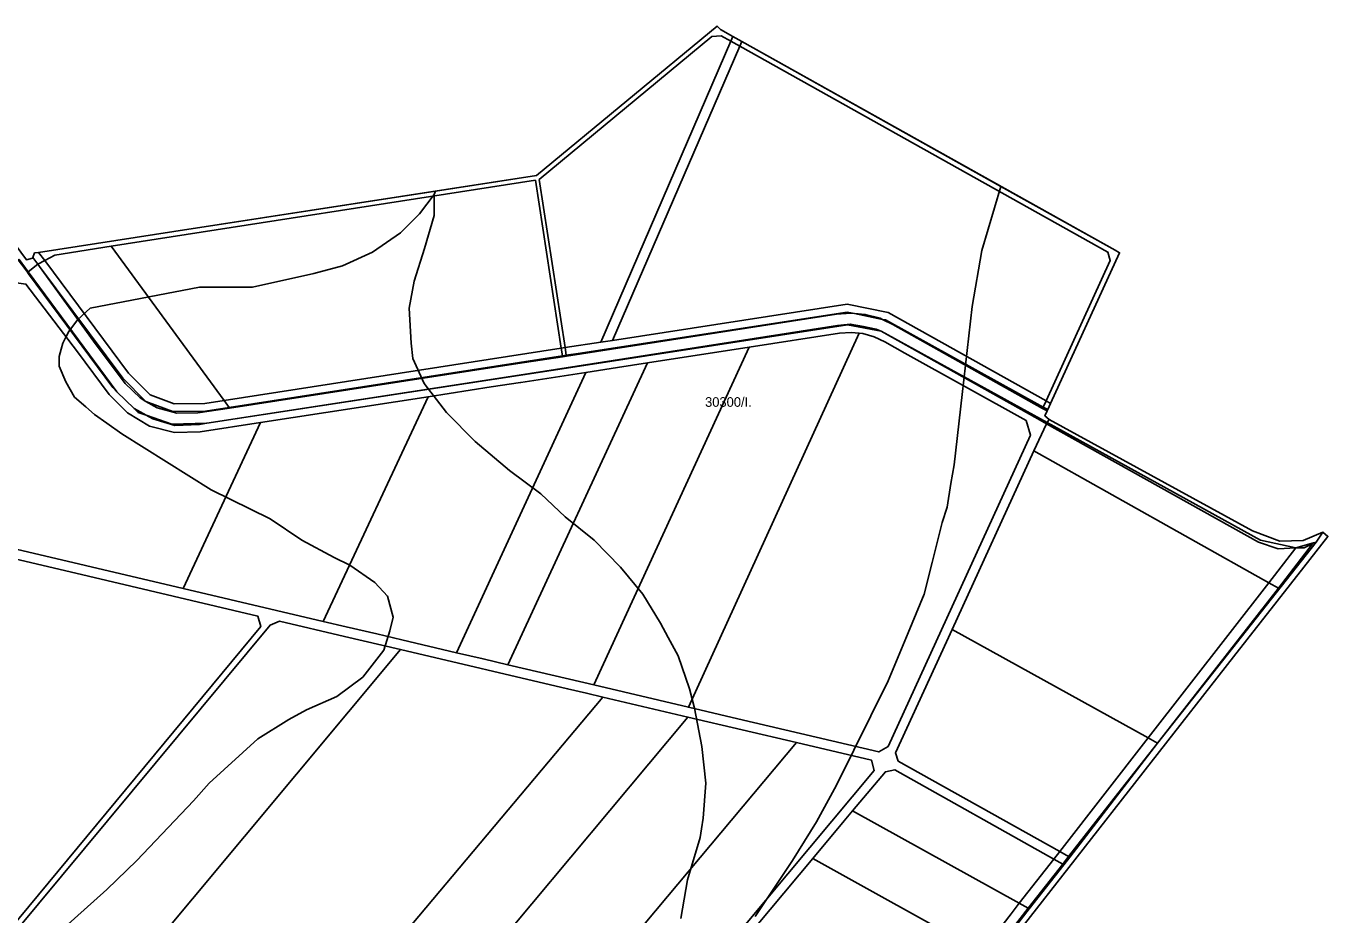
# Model space of a CAD drawing. Extents: x -541351 to -537540, y -1162694 to -1159725.
# Drawn here: x -538214 to -537540, y -1160910 to -1160450 of the extents above; entities that cross this region are included whole.
import ezdxf

# ---------------------------------------------------------------- set-up
doc = ezdxf.new("R2010")
doc.units = 0
for name, color, linetype in [('95560013', 7, 'Continuous'), ('95630013', 7, 'Continuous'), ('95640013', 7, 'Continuous'), ('95660013', 7, 'Continuous')]:
    doc.layers.add(name, color=color, linetype=linetype)

msp = doc.modelspace()

# ---------------------------------------------------------------- linework, layer by layer
at = {"layer": '95560013'}
for points in [[(-537854.65, -1160451.57), (-537848.19, -1160455.22), (-537849.25, -1160457.68), (-537854.31, -1160454.85), (-537859.18, -1160455.32), (-537948.53, -1160529.38), (-537935.11, -1160616.38), (-537937.08, -1160616.69), (-537950.51, -1160529.69), (-538170.18, -1160563.9), (-538199.28, -1160568.43), (-538204.55, -1160571.24), (-538207.69, -1160567.02), (-538137.75, -1160556.21), (-537949.87, -1160527.25), (-537856.38, -1160449.82)], [(-537854.31, -1160454.85), (-537849.25, -1160457.68), (-537916.68, -1160613.54), (-537935.11, -1160616.38), (-537948.53, -1160529.38), (-537859.18, -1160455.32)], [(-537652.84, -1160571.2), (-537686.06, -1160643.92), (-537767.82, -1160598.23), (-537789.01, -1160593.87), (-537910.61, -1160612.61), (-537844.69, -1160460.23), (-537654.02, -1160566.9)], [(-537648.03, -1160567.22), (-537683.74, -1160645.22), (-537686.06, -1160643.92), (-537652.84, -1160571.2), (-537654.02, -1160566.9), (-537844.69, -1160460.23), (-537843.64, -1160457.79), (-537650.31, -1160565.94)], [(-538111.7, -1160643.7), (-538170.18, -1160563.9), (-537950.51, -1160529.69), (-537937.08, -1160616.69)], [(-538204.55, -1160571.24), (-538199.28, -1160568.43), (-538170.18, -1160563.9), (-538111.7, -1160643.7), (-538121.61, -1160645.23), (-538137.51, -1160645.41), (-538149.93, -1160640.74), (-538161.11, -1160629.63)], [(-538150.21, -1160657.12), (-538137.31, -1160660.37), (-538124.12, -1160660), (-538092.74, -1160655.16), (-538132.87, -1160741.07), (-538332.3, -1160694.19), (-538330, -1160691.49), (-538326.82, -1160690.99), (-538270.16, -1160628.95), (-538250.29, -1160611.47), (-538227.76, -1160588.54), (-538220.32, -1160582.71), (-538214.26, -1160583.47), (-538187.49, -1160618.51), (-538171.08, -1160640.58), (-538161.72, -1160650.17)], [(-537787, -1160608.49), (-537782.88, -1160608.89), (-537871.24, -1160802.58), (-537920.22, -1160791.07), (-537839.88, -1160616.13), (-537793.09, -1160608.9)], [(-537685.53, -1160655.19), (-537682.14, -1160657.06), (-537575.01, -1160716.01), (-537556.76, -1160720.12), (-537565.98, -1160720.56), (-537576.03, -1160717.03), (-537685.89, -1160655.77), (-537690.34, -1160653.28), (-537771.5, -1160607.84)], [(-537767.83, -1160822.91), (-537772.69, -1160825.75), (-537845.69, -1160808.59), (-537871.24, -1160802.58), (-537782.88, -1160608.89), (-537781.03, -1160609.08), (-537775.16, -1160610.75), (-537769.61, -1160613.4), (-537759.18, -1160619.21), (-537696.41, -1160654.15), (-537694.22, -1160661.78)], [(-537964.76, -1160780.6), (-537892.46, -1160624.24), (-537839.88, -1160616.13), (-537920.22, -1160791.07), (-537932.87, -1160788.09)], [(-537892.46, -1160624.24), (-537964.76, -1160780.6), (-537977.6, -1160777.58), (-537991.33, -1160774.35), (-537924.33, -1160629.16), (-537908.06, -1160626.65)], [(-537958.23, -1160634.39), (-537957.98, -1160634.36), (-537924.33, -1160629.16), (-537991.33, -1160774.35), (-538019.61, -1160767.7), (-538032.56, -1160764.66), (-538048.38, -1160760.94), (-538060.4, -1160758.11), (-538006.06, -1160641.78), (-537973.3, -1160636.72)], [(-538060.4, -1160758.11), (-538132.87, -1160741.07), (-538092.74, -1160655.16), (-538006.06, -1160641.78)], [(-538138.75, -1160656.03), (-538120.6, -1160655.48), (-538124.4, -1160656.1), (-538137.11, -1160656.74), (-538148.62, -1160653.29), (-538151.96, -1160651.42)], [(-537570.77, -1160738.12), (-537692.33, -1160669.82), (-537685.89, -1160655.77), (-537576.03, -1160717.03), (-537565.98, -1160720.56), (-537556.76, -1160720.12)], [(-537734.71, -1160762.32), (-537692.33, -1160669.82), (-537570.77, -1160738.12), (-537633.29, -1160818.47)], [(-538252.72, -1160949.62), (-538431.35, -1160907.37), (-538420.84, -1160890.16), (-538402.43, -1160854.81), (-538370.7, -1160795.06), (-538364.45, -1160778.07), (-538353.36, -1160743.92), (-538341.15, -1160706.33), (-538338.41, -1160697.91), (-538194.31, -1160731.78), (-538094.21, -1160755.38), (-538092.7, -1160760.72), (-538248.03, -1160948.16)], [(-538087.82, -1160760.1), (-538082.9, -1160758.05), (-538049.38, -1160765.95), (-538020.28, -1160772.77), (-538181.83, -1160966.29), (-538235.36, -1160953.73), (-538241.69, -1160952.23), (-538243.57, -1160947.44)], [(-537762.62, -1160830.46), (-537764.01, -1160826.27), (-537734.71, -1160762.32), (-537633.29, -1160818.47), (-537679.04, -1160877.27)], [(-538181.83, -1160966.29), (-538020.28, -1160772.77), (-537933.84, -1160793.03), (-537923.96, -1160795.35), (-537915.59, -1160797.32), (-538077.91, -1160990.66), (-538085.86, -1160988.79)], [(-538045.37, -1160998.29), (-538077.91, -1160990.66), (-537915.59, -1160797.32), (-537871.51, -1160807.67), (-537952.32, -1160904.42), (-538033.13, -1161001.17)], [(-538033.13, -1161001.17), (-537952.32, -1160904.42), (-537871.51, -1160807.67), (-537815.26, -1160820.89), (-537977.34, -1161014.29)], [(-537815.26, -1160820.89), (-537776.51, -1160829.99), (-537775.04, -1160835.28), (-537853.06, -1160928.71), (-537931.08, -1161022.13), (-537935.72, -1161024.07), (-537977.34, -1161014.29)], [(-537764.46, -1160835.08), (-537682.11, -1160881.21), (-537699.93, -1160904.11), (-537786.25, -1160856.27), (-537769.22, -1160835.97)], [(-537806.91, -1160880.9), (-537790.61, -1160861.47), (-537786.25, -1160856.27), (-537699.93, -1160904.11), (-537704.14, -1160909.52), (-537719.59, -1160929.38)], [(-537806.91, -1160880.9), (-537719.59, -1160929.38), (-537754.86, -1160974.71), (-537843.94, -1160925.28)]]:
    msp.add_lwpolyline(points, close=True, dxfattribs=at)
for points in [[(-538214.91, -1160575.46), (-538213.5, -1160577.37), (-538212.88, -1160578.2), (-538169.34, -1160637.06), (-538167.16, -1160639.19), (-538158.3, -1160647.86), (-538156.16, -1160649.95), (-538151.96, -1160651.42), (-538148.62, -1160653.29), (-538137.11, -1160656.74), (-538124.4, -1160656.1), (-538120.6, -1160655.48), (-537927.57, -1160626.04), (-537788.88, -1160604.48), (-537771.5, -1160607.84), (-537690.34, -1160653.28), (-537685.89, -1160655.77), (-537692.33, -1160669.82), (-537734.71, -1160762.32), (-537764.01, -1160826.27), (-537762.62, -1160830.46), (-537679.04, -1160877.27), (-537682.11, -1160881.21), (-537764.46, -1160835.08), (-537769.22, -1160835.97), (-537786.25, -1160856.27), (-537790.61, -1160861.47), (-537806.91, -1160880.9), (-537843.94, -1160925.28)], [(-538332.3, -1160694.19), (-538132.87, -1160741.07), (-538060.4, -1160758.11), (-538048.38, -1160760.94), (-538032.56, -1160764.66), (-538019.61, -1160767.7), (-537991.33, -1160774.35), (-537977.6, -1160777.58), (-537964.76, -1160780.6), (-537932.87, -1160788.09), (-537920.22, -1160791.07), (-537871.24, -1160802.58), (-537845.69, -1160808.59), (-537772.69, -1160825.75), (-537767.83, -1160822.91), (-537694.22, -1160661.78), (-537696.41, -1160654.15), (-537759.18, -1160619.21), (-537769.61, -1160613.4), (-537775.16, -1160610.75), (-537781.03, -1160609.08), (-537782.88, -1160608.89), (-537787, -1160608.49), (-537793.09, -1160608.9), (-537839.88, -1160616.13), (-537892.46, -1160624.24), (-537908.06, -1160626.65), (-537924.33, -1160629.16), (-537957.98, -1160634.36), (-537958.23, -1160634.39), (-537973.3, -1160636.72), (-538006.06, -1160641.78), (-538092.74, -1160655.16), (-538124.12, -1160660), (-538137.31, -1160660.37), (-538150.21, -1160657.12), (-538161.72, -1160650.17), (-538171.08, -1160640.58), (-538187.49, -1160618.51), (-538214.26, -1160583.47)], [(-538248.03, -1160948.16), (-538092.7, -1160760.72), (-538094.21, -1160755.38), (-538194.31, -1160731.78), (-538338.41, -1160697.91)], [(-537853.06, -1160928.71), (-537775.04, -1160835.28), (-537776.51, -1160829.99), (-537815.26, -1160820.89), (-537871.51, -1160807.67), (-537915.59, -1160797.32), (-537923.96, -1160795.35), (-537933.84, -1160793.03), (-538020.28, -1160772.77), (-538049.38, -1160765.95), (-538082.9, -1160758.05), (-538087.82, -1160760.1), (-538243.57, -1160947.44)]]:
    msp.add_lwpolyline(points, dxfattribs=at)
at = {"layer": '95630013'}
msp.add_lwpolyline([(-538279, -1160482.96), (-538213.92, -1160570.92), (-538210.85, -1160570.08), (-538210.69, -1160569.68), (-538208.11, -1160573.15), (-538213.09, -1160577.05), (-538217.81, -1160570.66)], dxfattribs=at)
for points in [[(-538214.91, -1160575.46), (-538218.22, -1160570.98), (-538217.81, -1160570.66), (-538213.09, -1160577.05), (-538213.5, -1160577.37)], [(-537936.41, -1160621.05), (-537934.43, -1160620.74), (-537794.55, -1160599), (-537787.2, -1160598.56), (-537785.28, -1160598.72), (-537770.7, -1160601.72), (-537765.49, -1160604.46), (-537687.87, -1160647.87), (-537685.51, -1160649.08), (-537686.66, -1160651.61), (-537684.47, -1160653.51), (-537685.53, -1160655.19), (-537771.5, -1160607.84), (-537774.09, -1160606.83), (-537780.62, -1160605.35), (-537787.44, -1160604.21), (-537794.13, -1160604.91), (-537958.92, -1160630.57), (-538120.6, -1160655.48), (-538138.75, -1160656.03), (-538151.96, -1160651.42), (-538158.3, -1160647.86), (-538167.16, -1160639.19), (-538213.09, -1160577.05), (-538208.11, -1160573.15), (-538207.25, -1160574.31), (-538179.34, -1160612.95), (-538162.82, -1160634.9), (-538155.15, -1160642.4), (-538152.14, -1160644.18), (-538146.38, -1160647.61), (-538136.17, -1160650.23), (-538125.28, -1160650.17), (-538108.81, -1160647.63), (-537959.53, -1160624.65)], [(-538164.14, -1160632.26), (-538152.14, -1160644.18), (-538155.15, -1160642.4), (-538162.82, -1160634.9), (-538179.34, -1160612.95), (-538207.25, -1160574.31)], [(-538169.34, -1160637.06), (-538212.88, -1160578.2), (-538213.5, -1160577.37), (-538213.09, -1160577.05), (-538167.16, -1160639.19)], [(-537785.28, -1160598.72), (-537787.2, -1160598.56), (-537794.55, -1160599), (-537934.43, -1160620.74), (-537934.5, -1160620.33), (-537928.39, -1160619.39), (-537789.11, -1160597.93)], [(-537687.87, -1160647.87), (-537765.49, -1160604.46), (-537770.7, -1160601.72), (-537769.21, -1160602.03), (-537687.55, -1160647.19)], [(-537788.88, -1160604.48), (-537927.57, -1160626.04), (-538120.6, -1160655.48), (-537958.92, -1160630.57), (-537794.13, -1160604.91), (-537787.44, -1160604.21), (-537780.62, -1160605.35), (-537774.09, -1160606.83), (-537771.5, -1160607.84)], [(-537936.47, -1160620.64), (-537936.41, -1160621.05), (-537959.53, -1160624.65), (-538108.81, -1160647.63), (-538109.03, -1160647.34)], [(-537934.5, -1160620.33), (-537934.43, -1160620.74), (-537936.41, -1160621.05), (-537936.47, -1160620.64)], [(-538158.3, -1160647.86), (-538151.96, -1160651.42), (-538156.16, -1160649.95)], [(-538136.17, -1160650.23), (-538146.38, -1160647.61), (-538152.14, -1160644.18), (-538138.21, -1160649.42), (-538121.28, -1160649.23), (-538109.03, -1160647.34), (-538108.81, -1160647.63), (-538125.28, -1160650.17)], [(-537685.51, -1160649.08), (-537687.87, -1160647.87), (-537687.55, -1160647.19), (-537685.23, -1160648.47)], [(-537684.47, -1160653.51), (-537579.13, -1160711.27), (-537565.07, -1160716.59), (-537552.97, -1160716.32), (-537542.86, -1160712.01), (-537546.25, -1160717.06), (-537547.58, -1160717.45), (-537556.76, -1160720.12), (-537575.01, -1160716.01), (-537682.14, -1160657.06), (-537685.53, -1160655.19)], [(-537552.67, -1160730.05), (-537589.07, -1160776.48), (-537674.22, -1160885.61), (-537766.11, -1161003.04), (-537768.34, -1161000.98), (-537767.32, -1160999.7), (-537749.91, -1160977.46), (-537714.27, -1160932.34), (-537698.94, -1160912.41), (-537694.76, -1160906.98), (-537676.89, -1160884.14), (-537673.82, -1160880.18), (-537628.36, -1160821.2), (-537546.25, -1160717.06), (-537542.86, -1160712.01), (-537540.13, -1160714.12)], [(-537673.82, -1160880.18), (-537674.39, -1160879.87), (-537648.96, -1160847.33), (-537628.36, -1160821.2)], [(-537676.89, -1160884.14), (-537694.76, -1160906.98), (-537695.33, -1160906.66), (-537677.47, -1160883.81)], [(-537674.39, -1160879.87), (-537673.82, -1160880.18), (-537676.89, -1160884.14), (-537677.47, -1160883.81)], [(-537715.05, -1160931.9), (-537699.56, -1160912.07), (-537695.33, -1160906.66), (-537694.76, -1160906.98), (-537698.94, -1160912.41), (-537714.27, -1160932.34)]]:
    msp.add_lwpolyline(points, close=True, dxfattribs=at)
at = {"layer": '95640013'}
for points in [[(-537910.61, -1160612.61), (-537916.68, -1160613.54), (-537849.25, -1160457.68), (-537844.69, -1160460.23)], [(-537843.64, -1160457.79), (-537844.69, -1160460.23), (-537849.25, -1160457.68), (-537848.19, -1160455.22)], [(-538210.69, -1160569.68), (-538209.76, -1160567.34), (-538207.69, -1160567.02), (-538204.55, -1160571.24), (-538208.11, -1160573.15)], [(-538207.25, -1160574.31), (-538208.11, -1160573.15), (-538204.55, -1160571.24), (-538161.11, -1160629.63), (-538149.93, -1160640.74), (-538137.51, -1160645.41), (-538121.61, -1160645.23), (-538111.7, -1160643.7), (-538109.03, -1160647.34), (-538121.28, -1160649.23), (-538138.21, -1160649.42), (-538152.14, -1160644.18), (-538164.14, -1160632.26)], [(-537785.28, -1160598.72), (-537789.11, -1160597.93), (-537928.39, -1160619.39), (-537934.5, -1160620.33), (-537935.11, -1160616.38), (-537916.68, -1160613.54), (-537910.61, -1160612.61), (-537789.01, -1160593.87), (-537767.82, -1160598.23), (-537686.06, -1160643.92), (-537687.55, -1160647.19), (-537769.21, -1160602.03), (-537770.7, -1160601.72), (-537771.96, -1160601.05), (-537779.69, -1160599.17)], [(-537785.28, -1160598.72), (-537779.69, -1160599.17), (-537771.96, -1160601.05), (-537770.7, -1160601.72)], [(-538109.03, -1160647.34), (-538111.7, -1160643.7), (-537937.08, -1160616.69), (-537936.47, -1160620.64)], [(-537937.08, -1160616.69), (-537935.11, -1160616.38), (-537934.5, -1160620.33), (-537936.47, -1160620.64)], [(-537683.74, -1160645.22), (-537685.23, -1160648.47), (-537687.55, -1160647.19), (-537686.06, -1160643.92)], [(-537565.82, -1160740.9), (-537548.08, -1160718.02), (-537552.5, -1160720.02), (-537556.76, -1160720.12), (-537547.58, -1160717.45), (-537546.25, -1160717.06), (-537628.36, -1160821.2)], [(-537548.08, -1160718.02), (-537565.82, -1160740.9), (-537570.77, -1160738.12), (-537556.76, -1160720.12), (-537552.5, -1160720.02)], [(-537633.29, -1160818.47), (-537570.77, -1160738.12), (-537565.82, -1160740.9), (-537628.36, -1160821.2)], [(-537628.36, -1160821.2), (-537648.96, -1160847.33), (-537674.39, -1160879.87), (-537679.04, -1160877.27), (-537633.29, -1160818.47)], [(-537677.47, -1160883.81), (-537682.11, -1160881.21), (-537679.04, -1160877.27), (-537674.39, -1160879.87)], [(-537695.33, -1160906.66), (-537699.93, -1160904.11), (-537682.11, -1160881.21), (-537677.47, -1160883.81)], [(-537699.93, -1160904.11), (-537695.33, -1160906.66), (-537699.56, -1160912.07), (-537715.05, -1160931.9), (-537719.59, -1160929.38), (-537704.14, -1160909.52)]]:
    msp.add_lwpolyline(points, close=True, dxfattribs=at)
at = {"layer": '95660013'}
for points in [[(-537875.12, -1160912), (-537871.81, -1160892), (-537865.19, -1160870), (-537864.49, -1160865.56), (-537863.62, -1160860), (-537862.31, -1160842), (-537864.37, -1160823), (-537868.12, -1160803), (-537870.62, -1160793), (-537876.62, -1160776), (-537881.66, -1160766.56), (-537885.69, -1160759), (-537894.81, -1160744), (-537906.37, -1160730), (-537920.12, -1160716), (-537935, -1160704), (-537947.62, -1160692), (-537963.81, -1160680), (-537981.62, -1160665), (-537996.5, -1160650), (-538008.12, -1160635), (-538013.87, -1160622), (-538014.81, -1160614), (-538015.81, -1160596), (-538013.31, -1160582), (-538007.87, -1160565), (-538002.87, -1160548), (-538002.87, -1160537), (-538002.24, -1160535.32), (-537949.87, -1160527.25), (-537856.38, -1160449.82), (-537854.65, -1160451.57), (-537848.19, -1160455.22), (-537843.64, -1160457.79), (-537709.45, -1160532.86), (-537719.37, -1160566), (-537724.37, -1160595), (-537729.55, -1160640.56), (-537733.69, -1160677), (-537735.33, -1160686.78), (-537737.37, -1160699), (-537739.87, -1160707), (-537745.05, -1160727.56), (-537749.19, -1160744), (-537757.49, -1160764), (-537767.87, -1160789), (-537794.62, -1160843), (-537804.87, -1160862), (-537817.37, -1160882), (-537836.62, -1160911)], [(-538279, -1160482.96), (-538213.92, -1160570.92), (-538210.85, -1160570.08), (-538210.69, -1160569.68), (-538209.76, -1160567.34), (-538207.69, -1160567.02), (-538137.75, -1160556.21), (-538002.24, -1160535.32), (-538002.87, -1160537), (-538010.5, -1160547), (-538020.37, -1160557), (-538034.87, -1160567), (-538050.31, -1160574), (-538065.12, -1160578), (-538096.87, -1160585), (-538124.37, -1160585), (-538181, -1160596), (-538187.5, -1160602), (-538192.12, -1160608), (-538193.83, -1160611.33), (-538195.19, -1160614), (-538196.05, -1160617.11), (-538197.12, -1160621), (-538197.12, -1160626), (-538193.62, -1160634), (-538189.12, -1160642), (-538183.33, -1160647), (-538178.69, -1160651), (-538172.44, -1160655.44), (-538164.62, -1160661), (-538118.31, -1160690), (-538087.87, -1160705), (-538071.37, -1160716), (-538054.62, -1160725), (-538046.62, -1160729), (-538033.62, -1160738), (-538027.12, -1160745), (-538024.12, -1160756), (-538025.87, -1160763), (-538029, -1160773), (-538039.87, -1160787), (-538053.31, -1160797), (-538069, -1160804), (-538078.12, -1160809), (-538094.19, -1160819), (-538119.37, -1160842), (-538127.5, -1160851), (-538156.81, -1160882), (-538172.37, -1160897), (-538199.19, -1160921)], [(-537836.62, -1160911), (-537817.37, -1160882), (-537804.87, -1160862), (-537794.62, -1160843), (-537767.87, -1160789), (-537757.49, -1160764), (-537749.19, -1160744), (-537745.05, -1160727.56), (-537739.87, -1160707), (-537737.37, -1160699), (-537735.33, -1160686.78), (-537733.69, -1160677), (-537729.55, -1160640.56), (-537724.37, -1160595), (-537719.37, -1160566), (-537709.45, -1160532.86), (-537650.31, -1160565.94), (-537648.03, -1160567.22), (-537683.74, -1160645.22), (-537685.23, -1160648.47), (-537685.51, -1160649.08), (-537686.66, -1160651.61), (-537684.47, -1160653.51), (-537579.13, -1160711.27), (-537565.07, -1160716.59), (-537552.97, -1160716.32), (-537542.86, -1160712.01), (-537540.13, -1160714.12), (-537552.67, -1160730.05), (-537589.07, -1160776.48), (-537674.22, -1160885.61), (-537766.11, -1161003.04)], [(-538199.19, -1160921), (-538172.37, -1160897), (-538156.81, -1160882), (-538127.5, -1160851), (-538119.37, -1160842), (-538094.19, -1160819), (-538078.12, -1160809), (-538069, -1160804), (-538053.31, -1160797), (-538039.87, -1160787), (-538029, -1160773), (-538025.87, -1160763), (-538024.12, -1160756), (-538027.12, -1160745), (-538033.62, -1160738), (-538046.62, -1160729), (-538054.62, -1160725), (-538071.37, -1160716), (-538087.87, -1160705), (-538118.31, -1160690), (-538164.62, -1160661), (-538172.44, -1160655.44), (-538178.69, -1160651), (-538183.33, -1160647), (-538189.12, -1160642), (-538193.62, -1160634), (-538197.12, -1160626), (-538197.12, -1160621), (-538196.05, -1160617.11), (-538195.19, -1160614), (-538193.83, -1160611.33), (-538192.12, -1160608), (-538187.5, -1160602), (-538181, -1160596), (-538124.37, -1160585), (-538096.87, -1160585), (-538065.12, -1160578), (-538050.31, -1160574), (-538034.87, -1160567), (-538020.37, -1160557), (-538010.5, -1160547), (-538002.87, -1160537), (-538002.87, -1160548), (-538007.87, -1160565), (-538013.31, -1160582), (-538015.81, -1160596), (-538014.81, -1160614), (-538013.87, -1160622), (-538008.12, -1160635), (-537996.5, -1160650), (-537981.62, -1160665), (-537963.81, -1160680), (-537947.62, -1160692), (-537935, -1160704), (-537920.12, -1160716), (-537906.37, -1160730), (-537894.81, -1160744), (-537885.69, -1160759), (-537881.66, -1160766.56), (-537876.62, -1160776), (-537870.62, -1160793), (-537868.12, -1160803), (-537864.37, -1160823), (-537862.31, -1160842), (-537863.62, -1160860), (-537864.49, -1160865.56), (-537865.19, -1160870), (-537871.81, -1160892), (-537875.12, -1160912)]]:
    msp.add_lwpolyline(points, dxfattribs=at)

# ---------------------------------------------------------------- texts
msp.add_text('30300/I.', height=5, rotation=0, dxfattribs=at).set_placement((-537862.63, -1160647.02))

doc.saveas('drawing.dxf')
